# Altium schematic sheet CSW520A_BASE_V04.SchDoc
size A2
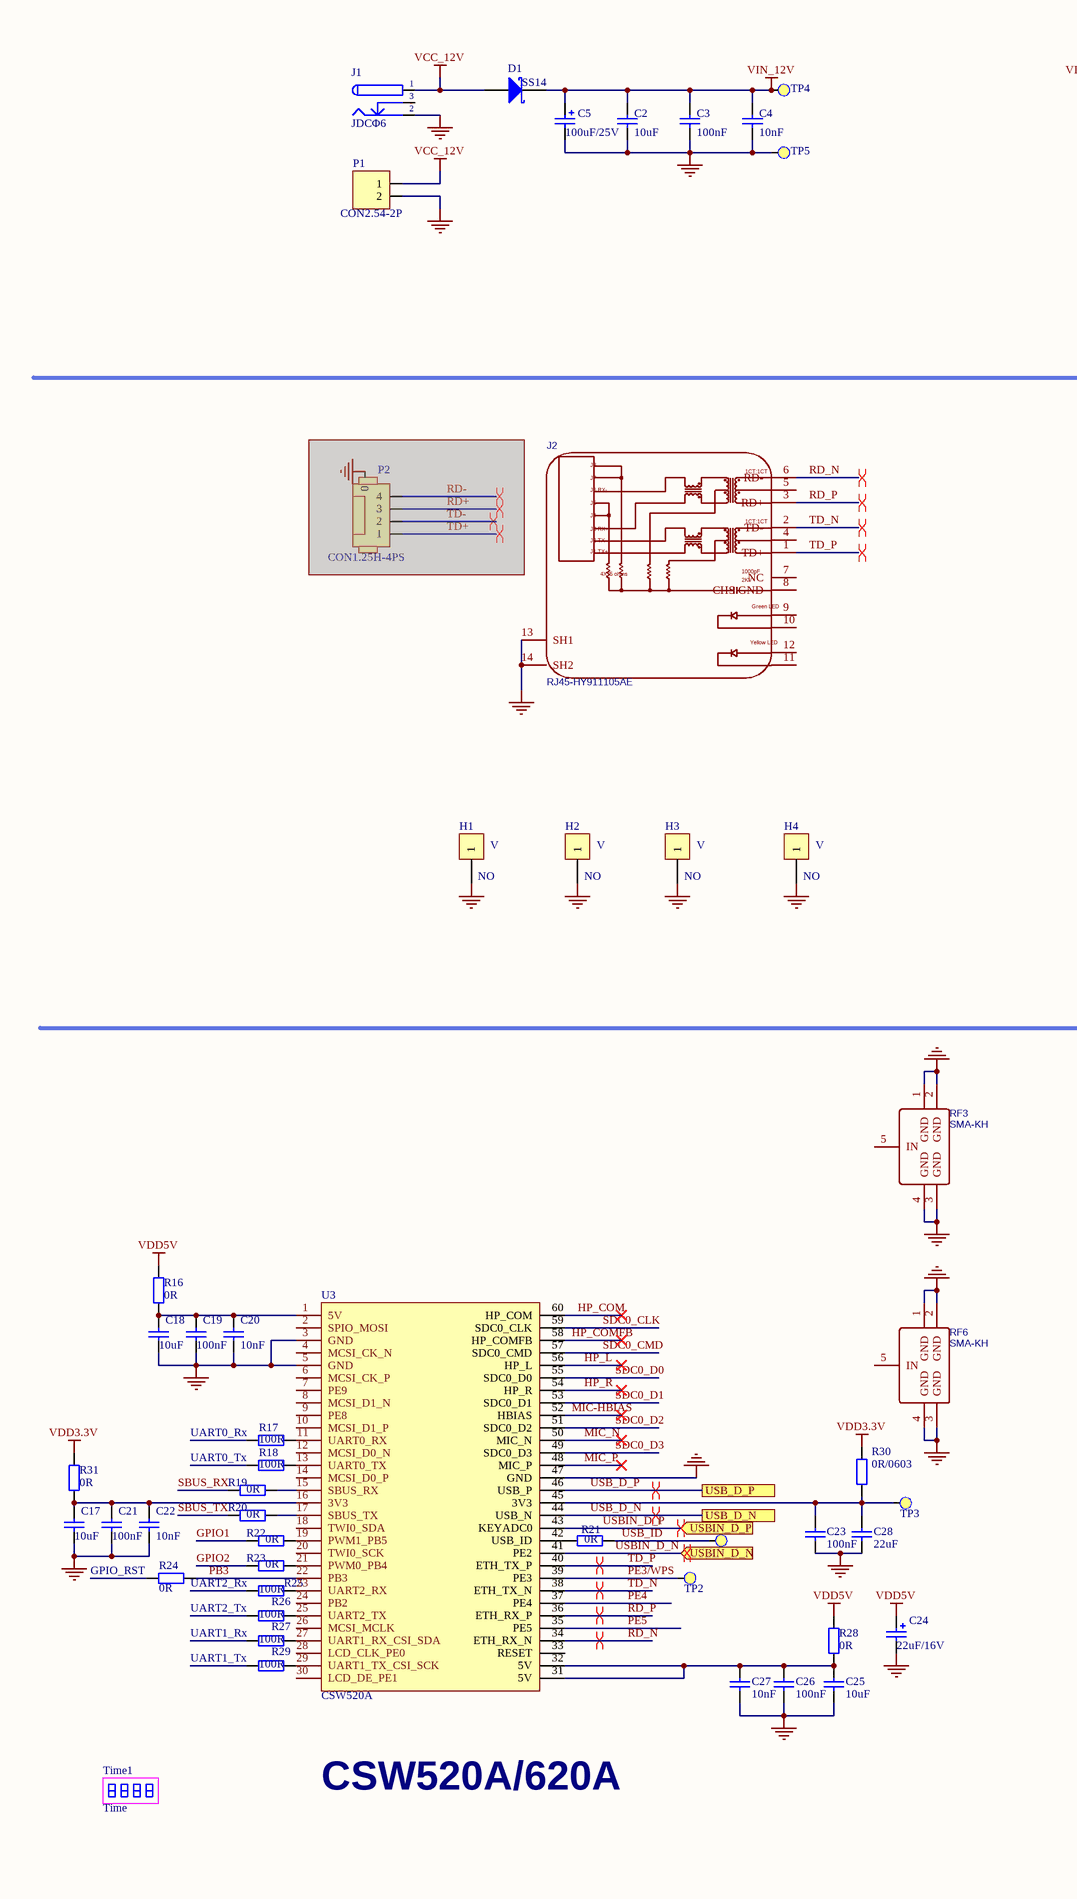
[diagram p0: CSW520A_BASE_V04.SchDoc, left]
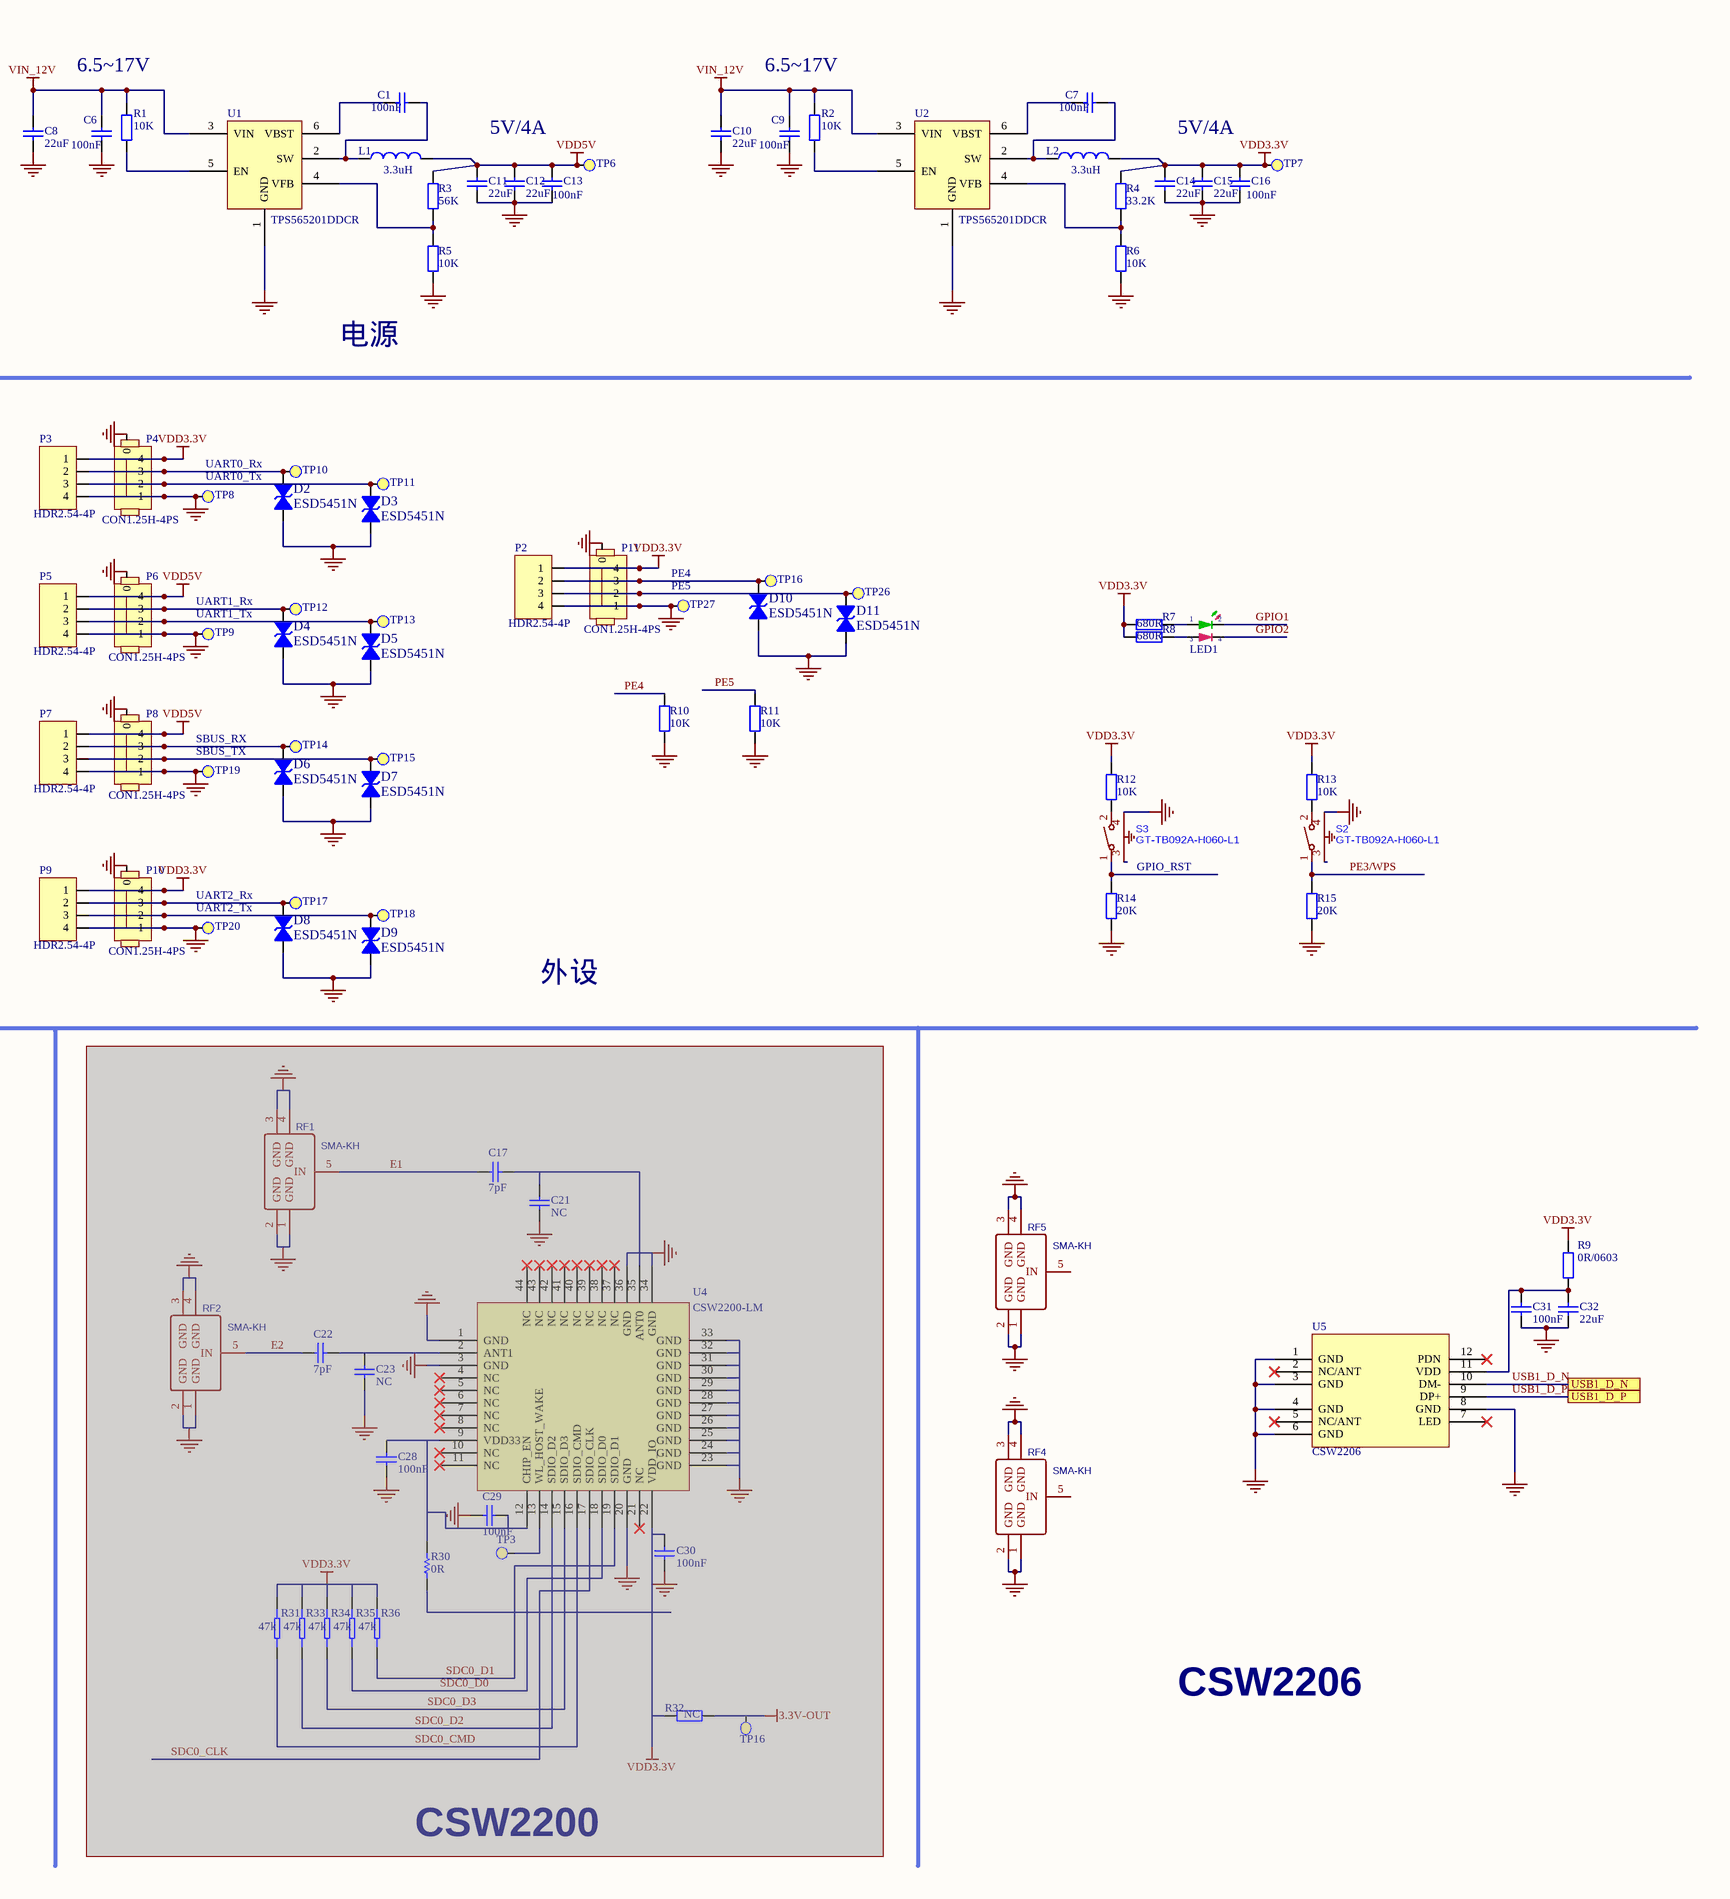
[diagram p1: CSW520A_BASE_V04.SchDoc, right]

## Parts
(Parts that share a designator on the sheet are numbered #1, #2 ... from top to bottom, then left to right.)
C1  100nF  [C-0402_1]
C2  10uF  [C-0805]
C3  100nF  [C-0603_1]
C4  10nF  [C-0402_1]
C5  100uF/25V  [CE100U25V-SM]
C6  100nF  [C-0402_1]
C7  100nF  [C-0402_1]
C8  22uF  [C-1206]
C9  100nF  [C-0402_1]
C10  22uF  [C-1206]
C11  22uF  [C-0805]
C12  22uF  [C-0805]
C13  100nF  [C-0402_1]
C14  22uF  [C-0805]
C15  22uF  [C-0805]
C16  100nF  [C-0402_1]
C17#1  7pF  [C-0402_1]  (masked out: inside a compile mask, not in the netlist)
C17#2  10uF  [C-0805]
C18  10uF  [C-0805]
C19  100nF  [C-0402_1]
C20  10nF  [C-0402_1]
C21#1  NC  [C-0402_1]  (masked out: inside a compile mask, not in the netlist)
C21#2  100nF  [C-0402_1]
C22#1  7pF  [C-0402_1]  (masked out: inside a compile mask, not in the netlist)
C22#2  10nF  [C-0402_1]
C23#1  NC  [C-0402_1]  (masked out: inside a compile mask, not in the netlist)
C23#2  100nF  [C-0402_1]
C24  22uF/16V  [AVX-B]
C25  10uF  [C-0805]
C26  100nF  [C-0402_1]
C27  10nF  [C-0402_1]
C28#1  100nF  [C-0402_1]  (masked out: inside a compile mask, not in the netlist)
C28#2  22uF  [C-0805]
C29  100nF  [C-0402_1]  (masked out: inside a compile mask, not in the netlist)
C30  100nF  [C-0402_1]  (masked out: inside a compile mask, not in the netlist)
C31  100nF  [C-0402_1]
C32  22uF  [C-0805]
D1  SS14  [DO-214AC]
D2  ESD5451N  [ESD-0402]
D3  ESD5451N  [ESD-0402]
D4  ESD5451N  [ESD-0402]
D5  ESD5451N  [ESD-0402]
D6  ESD5451N  [ESD-0402]
D7  ESD5451N  [ESD-0402]
D8  ESD5451N  [ESD-0402]
D9  ESD5451N  [ESD-0402]
D10  ESD5451N  [ESD-0402]
D11  ESD5451N  [ESD-0402]
H1  V  SPEC: NO  [PAD-1]
H2  V  SPEC: NO  [PAD-1]
H3  V  SPEC: NO  [PAD-1]
H4  V  SPEC: NO  [PAD-1]
J1  JDCΦ6  [DCΦ6]
J2  RJ45-HY911105AE  [RJ45-TH_HR913129A]
L1  3.3uH  [L-5020]
L2  3.3uH  [L-5020]
LED1  MHK2310GEBTD  [LED-2310-2PCS]  (value not drawn)
P1  CON2.54-2P  [CON2.54H-2P]
P2#1  CON1.25H-4PS  [CON1.25-4PS_GH]  (masked out: inside a compile mask, not in the netlist)
P2#2  HDR2.54-4P  [HDR2.54-4P]
P3  HDR2.54-4P  [HDR2.54-4P]
P4  CON1.25H-4PS  [CON1.25-4PS_GH]
P5  HDR2.54-4P  [HDR2.54-4P]
P6  CON1.25H-4PS  [CON1.25-4PS_GH]
P7  HDR2.54-4P  [HDR2.54-4P]
P8  CON1.25H-4PS  [CON1.25-4PS_GH]
P9  HDR2.54-4P  [HDR2.54-4P]
P10  CON1.25H-4PS  [CON1.25-4PS_GH]
P11  CON1.25H-4PS  [CON1.25-4PS_GH]
R1  10K  [R-0402_1]
R2  10K  [R-0402_1]
R3  56K  [R-0402_1]
R4  33.2K  [R-0402_1]
R5  10K  [R-0402_1]
R6  10K  [R-0402_1]
R7  680R  [R-0402_1]
R8  680R  [R-0402_1]
R9  0R/0603  [R-0603]
R10  10K  [R-0402_1]
R11  10K  [R-0402_1]
R12  10K  [R-0402_1]
R13  10K  [R-0402_1]
R14  20K  [R-0402_1]
R15  20K  [R-0402_1]
R16  0R  [R-1206]
R17  100R  [R-0402_1]
R18  100R  [R-0402_1]
R19  0R  [R-0402_1]
R20  0R  [R-0402_1]
R21  0R  [R-0402_1]
R22  0R  [R-0402_1]
R23  0R  [R-0402_1]
R24  0R  [R-0402_1]
R25  100R  [R-0402_1]
R26  100R  [R-0402_1]
R27  100R  [R-0402_1]
R28  0R  [R-1206]
R29  100R  [R-0402_1]
R30#1  0R/0603  [R-0603]
R30#2  0R  [R-0603]  (masked out: inside a compile mask, not in the netlist)
R31#1  0R  [R-1206]
R31#2  47k  [R-0402_1]  (masked out: inside a compile mask, not in the netlist)
R32  NC  [R-0603]  (masked out: inside a compile mask, not in the netlist)
R33  47k  [R-0402_1]  (masked out: inside a compile mask, not in the netlist)
R34  47k  [R-0402_1]  (masked out: inside a compile mask, not in the netlist)
R35  47k  [R-0402_1]  (masked out: inside a compile mask, not in the netlist)
R36  47k  [R-0402_1]  (masked out: inside a compile mask, not in the netlist)
RF1  SMA-KH  [SMA-KH]  (masked out: inside a compile mask, not in the netlist)
RF2  SMA-KH  [SMA-KH]  (masked out: inside a compile mask, not in the netlist)
RF3  SMA-KH  [SMA-KH]
RF4  SMA-KH  [SMA-KH]
RF5  SMA-KH  [SMA-KH]
RF6  SMA-KH  [SMA-KH]
S2  GT-TB092A-H060-L1  [K-4.5×.4.5x6.0-SH]
S3  GT-TB092A-H060-L1  [K-4.5×.4.5x6.0-SH]
Time1  Time  [Ni7seg]
TP1  TP  [Test-Point]  (value not drawn)
TP2  TP  [Test-Point]  (value not drawn)
TP3#1  TP  [Test-Point]  (value not drawn)
TP3#2  TP  [Test-Point]  (value not drawn)  (masked out: inside a compile mask, not in the netlist)
TP4  TP  [Test-Point]  (value not drawn)
TP5  TP  [Test-Point]  (value not drawn)
TP6  TP  [Test-Point]  (value not drawn)
TP7  TP  [Test-Point]  (value not drawn)
TP8  TP  [Test-Point]  (value not drawn)
TP9  TP  [Test-Point]  (value not drawn)
TP10  TP  [Test-Point]  (value not drawn)
TP11  TP  [Test-Point]  (value not drawn)
TP12  TP  [Test-Point]  (value not drawn)
TP13  TP  [Test-Point]  (value not drawn)
TP14  TP  [Test-Point]  (value not drawn)
TP15  TP  [Test-Point]  (value not drawn)
TP16#1  TP  [Test-Point]  (value not drawn)
TP16#2  TP  [Test-Point]  (value not drawn)  (masked out: inside a compile mask, not in the netlist)
TP17  TP  [Test-Point]  (value not drawn)
TP18  TP  [Test-Point]  (value not drawn)
TP19  TP  [Test-Point]  (value not drawn)
TP20  TP  [Test-Point]  (value not drawn)
TP26  TP  [Test-Point]  (value not drawn)
TP27  TP  [Test-Point]  (value not drawn)
U1  TPS565201DDCR  [SOT23-6]
U2  TPS565201DDCR  [SOT23-6]
U3  CSW520A  [CSW520]
U4  CSW2200-LM  [CSW2200]  (masked out: inside a compile mask, not in the netlist)
U5  CSW2206  [CSW2206]

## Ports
USB1_D_N, USB1_D_P, USB_D_N, USB_D_P, USBIN_D_N (in), USBIN_D_P (in)

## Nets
GND: C2.1 C3.1 C4.1 C5.2 C6.1 C8.1 C9.1 C10.1 C11.1 C12.1 C13.1 C14.1 C15.1 C16.1 C17#2.1 C18.1 C19.1 C20.2 C21#2.1 C22#2.2 C23#2.2 C24.2 C25.1 C26.1 C27.2 C28#2.1 C31.2 C32.1 D2.2(K) D3.2(K) D4.2(K) D5.2(K) D6.2(K) D7.2(K) D8.2(K) D9.2(K) D10.2(K) D11.2(K) H1.1 H2.1 H3.1 H4.1 J1.2 J2.13(SH1) J2.14(SH2) P1.2 P2#2.4 P3.4 P4.0 P4.1 P5.4 P6.0 P6.1 P7.4 P8.0 P8.1 P9.4 P10.0 P10.1 P11.0 P11.1 R5.1 R6.1 R10.1 R11.1 R14.1 R15.1 RF3.1(GND) RF3.2(GND) RF3.3(GND) RF3.4(GND) RF4.1(GND) RF4.2(GND) RF4.3(GND) RF4.4(GND) RF5.1(GND) RF5.2(GND) RF5.3(GND) RF5.4(GND) RF6.1(GND) RF6.2(GND) RF6.3(GND) RF6.4(GND) S2.4(B) S3.4(B) TP5.0 TP8.0 TP9.0 TP19.0 TP20.0 TP27.0 U1.1(GND) U2.1(GND) U3.3(GND) U3.5(GND) U3.47(GND) U5.1(GND) U5.3(GND) U5.4(GND) U5.6(GND) U5.8(GND)
VCC_12V: D1.1(A) J1.1 P1.1
VDD3.3V: C14.2 C15.2 C16.2 L2.2 P2#2.1 P3.1 P4.4 P9.1 P10.4 P11.4 R4.2 R7.2 R8.2 R9.1 R12.2 R13.2 R30#1.1 R31#1.2 TP7.0
VDD5V: C11.2 C12.2 C13.2 C24.1 L1.2 P5.1 P6.4 P7.1 P8.4 R3.2 R16.2 R28.2 TP6.0
VIN_12V: C2.2 C3.2 C4.2 C5.1 C6.2 C8.2 C9.2 C10.2 D1.2(K) R1.1 R2.1 TP4.0 U1.3(VIN) U2.3(VIN)
GPIO1: LED1.2(G) R22.1
GPIO2: LED1.4(R) R23.1
GPIO_RST: R14.2 R24.2 S3.1(C)
HP_COM: U3.60(HP_COM)
HP_COMFB: U3.58(HP_COMFB)
HP_L: U3.56(HP_L)
HP_R: U3.54(HP_R)
MIC-HBIAS: U3.52(HBIAS)
MIC_N: U3.50(MIC_N)
MIC_P: U3.48(MIC_P)
PB3: R24.1 U3.22(PB3)
PE3/WPS: R15.2 S2.1(C) TP2.0 U3.39(PE3)
PE4: D10.1(A) P2#2.2 P11.3 R10.2 TP16#1.0 U3.37(PE4)
PE5: D11.1(A) P2#2.3 P11.2 R11.2 TP26.0 U3.35(PE5)
RD_N: J2.6(RD-) U3.34(ETH_RX_N)
RD_P: J2.3(RD+) U3.36(ETH_RX_P)
SBUS_RX: D6.1(A) P7.2 P8.3 R19.1 TP14.0
SBUS_TX: D7.1(A) P7.3 P8.2 R20.1 TP15.0
SDC0_CLK: U3.59(SDC0_CLK)
SDC0_CMD: U3.57(SDC0_CMD)
SDC0_D0: U3.55(SDC0_D0)
SDC0_D1: U3.53(SDC0_D1)
SDC0_D2: U3.51(SDC0_D2)
SDC0_D3: U3.49(SDC0_D3)
TD_N: J2.2(TD-) U3.38(ETH_TX_N)
TD_P: J2.1(TD+) U3.40(ETH_TX_P)
UART0_Rx: D2.1(A) P3.2 P4.3 R17.2 TP10.0
UART0_Tx: D3.1(A) P3.3 P4.2 R18.2 TP11.0
UART1_Rx: D4.1(A) P5.2 P6.3 R27.2 TP12.0
UART1_Tx: D5.1(A) P5.3 P6.2 R29.2 TP13.0
UART2_Rx: D8.1(A) P9.2 P10.3 R25.2 TP17.0
UART2_Tx: D9.1(A) P9.3 P10.2 R26.2 TP18.0
USB1_D_N: U5.10(DM-) ; port USB1_D_N
USB1_D_P: U5.9(DP+) ; port USB1_D_P
USB_D_N: U3.44(USB_N) ; port USB_D_N
USB_D_P: U3.46(USB_P) ; port USB_D_P
USB_ID: R21.2 TP1.0
USBIN_D_N: U3.41(PE2) ; port USBIN_D_N
USBIN_D_P: U3.43(KEYADC0) ; port USBIN_D_P
NetC1_1: C1.1 L1.1 U1.2(SW)
NetC1_2: C1.2 U1.6(VBST)
NetC7_1: C7.1 L2.1 U2.2(SW)
NetC7_2: C7.2 U2.6(VBST)
NetC17#2_2: C17#2.2 C21#2.2 C22#2.1 R31#1.1 U3.16(3V3)
NetC18_2: C18.2 C19.2 C20.1 R16.1 U3.1(5V)
NetC23#2_1: C23#2.1 C28#2.2 R30#1.2 TP3#1.0 U3.45(3V3)
NetC25_2: C25.2 C26.2 C27.1 R28.1 U3.31(5V) U3.32(5V)
NetC31_1: C31.1 C32.2 R9.2 U5.11(VDD)
NetLED1_1: LED1.1(G) R7.1
NetLED1_3: LED1.3(R) R8.1
NetR1_2: R1.2 U1.5(EN)
NetR2_2: R2.2 U2.5(EN)
NetR3_1: R3.1 R5.2 U1.4(VFB)
NetR4_1: R4.1 R6.2 U2.4(VFB)
NetR12_1: R12.1 S3.2(D)
NetR13_1: R13.1 S2.2(D)
NetR17_1: R17.1 U3.11(UART0_RX)
NetR18_1: R18.1 U3.13(UART0_TX)
NetR19_2: R19.2 U3.15(SBUS_RX)
NetR20_2: R20.2 U3.17(SBUS_TX)
NetR21_1: R21.1 U3.42(USB_ID)
NetR22_2: R22.2 U3.19(PWM1_PB5)
NetR23_2: R23.2 U3.21(PWM0_PB4)
NetR25_1: R25.1 U3.23(UART2_RX)
NetR26_1: R26.1 U3.25(UART2_TX)
NetR27_1: R27.1 U3.27(UART1_RX_CSI_SDA)
NetR29_1: R29.1 U3.29(UART1_TX_CSI_SCK)

Not connected (* = marked no-connect by the designer): J1 3; J2 4 5 7(NC) 8(CHS_GND) 9 10 11 12; RF3 5(IN); RF4 5(IN); RF5 5(IN); RF6 5(IN); S2 3(A); S3 3(A); U3 2(SPIO_MOSI) 4(MCSI_CK_N) 6(MCSI_CK_P) 7(PE9) 8(MCSI_D1_N) 9(PE8) 10(MCSI_D1_P) 12(MCSI_D0_N) 14(MCSI_D0_P) 18(TWI0_SDA) 20(TWI0_SCK) 24(PB2) 26(MCSI_MCLK) 28(LCD_CLK_PE0) 30(LCD_DE_PE1) 33(RESET); U5 2(NC/ANT)* 5(NC/ANT)* 7(LED)* 12(PDN)*

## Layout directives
differential pair: (no net found under the mark), RD_N, RD_P, TD_N, TD_P, USB_D_N, USB_D_P, USBIN_D_N, USBIN_D_P

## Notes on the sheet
- 6.5
  7V
- 5V/4A
- 电源
- 外设
- CSW2206
- CSW520A/620A
- CSW2200

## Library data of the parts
C1 C6-C16 C20 C22#2 C27 = Cap: Capacitor
C2 = Cap: Capacitor; Value: 4.7uF/35V/0805
C3 = Cap: Capacitor; Value: 0.1uF/50V/0402
C4 = Cap: Capacitor; Value: 0.01uF/50V/0402
C5 C24 = Cap Pol1: Polarized Capacitor (Radial)
C17#1 = Cap Semi: Capacitor (Semiconductor SIM Model); Value: NC
C17#2 C18 C19 C21#2 C23#2 C25 C26 C28#1 C28#2 C29-C32 = CAP: Capacitor
C21#1 C23#1 = Cap Semi: Capacitor (Semiconductor SIM Model)
C22#1 = Cap Semi: Capacitor (Semiconductor SIM Model); Value: 100pF
D1 = D Schottky: Schottky Diode
D2-D11 = TVS: Schottky Diode
H1-H4 = con1
J1 = JDCΦ5: Low Voltage Power Supply Connector
J2 = RJ45-HY911105AE: BOM_Manufacturer: HANRUN
L1 L2 = Inductor: Code_IEC: 1005; Value: 6.8uH
LED1 = LED-D_2PCS
R1-R29 R30#1 R31#1 R32 = Res: Resistor
R30#2 = Res Semi: Semiconductor Resistor
R31#2 R33-R36 = R
RF1-RF6 = SMA-KH: BOM_Manufacturer: Shenzhen Kinghelm Elec; BOM_Manufacturer Part: KH-SMA-K513-G; Contributor: LCSC
S2 S3 = SW-PB-1
Time1 = Ni7seg: Multicell Battery
U1 U2 = TPS564201
U4 = 8192fs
